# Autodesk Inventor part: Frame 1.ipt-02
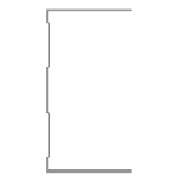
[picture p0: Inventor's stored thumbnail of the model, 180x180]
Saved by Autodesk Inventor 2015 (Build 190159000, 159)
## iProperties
Created: 2015-04
Part Number: Frame 1.ipt-02
Material: Aluminum 6061
Description: Kévin Novo
Document SubType Name: Modeling
Standard: Kevin
Designer: suporte
Standards Organization: Kevin
Language: en-US
Size Designation: (Unnamed 2)
Categories: <MemberInstance><Categories><Category DisplayName="Structural Shapes" InternalName="089c4875-fa83-4c05-b084-43b9cc11f5ed" Mnemonic="GRDR"><CategoryParameter Dis
Density: 2.7 g/cm^3
Appearance: Aluminum - Flat
IsCustomPart: 1
G_W: 50,000 mm
G_H: 75,000 mm
G_L: 518,599 mm
_CCFamilyMember: 2
_CCFamilyDisplayName: Kévin - Kévin Novo
_FrameMemberDoc: Frame Member File
_Version: 15.0.0
_GetPNFromCC: 1
Author: suporte
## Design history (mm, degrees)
node "Start Plane"
node "End Plane"
sketch "Sketch"
  geometry: L1 (24.7, 37.5)-(24.7, 36.9); L2 (24.7, 36.9)-(-24.7, 36.9); L3 (-24.7, -36.9)-(24.7, -36.9); L4 (24.7, -36.9)-(24.7, -37.5); L5 (24.7, -37.5)-(-25.3, -37.5); L6 (-25.3, 37.5)-(24.7, 37.5); L7 (-24.7, 36.9)-(-24.7, 31.9); L8 (-24.7, 31.9)-(-23.3, 30.5); L9 (-23.3, 30.5)-(-23.3, 10.934); L10 (-23.3, 10.934)-(-24.7, 9.534); L11 (-24.7, 9.534)-(-24.7, -9.534); L12 (-24.7, -9.534)-(-23.3, -10.934); L13 (-23.3, -10.934)-(-23.3, -30.5); L14 (-23.3, -30.5)-(-24.7, -31.9); L15 (-24.7, -31.9)-(-24.7, -36.9); L16 (-25.3, -37.5)-(-25.3, -31.651); L17 (-25.3, -31.651)-(-23.9, -30.251); L18 (-23.9, -30.251)-(-23.9, -11.183); L19 (-23.9, -11.183)-(-25.3, -9.783); L20 (-25.3, -9.783)-(-25.3, 9.783); L21 (-25.3, 9.783)-(-23.9, 11.183); L22 (-23.9, 11.183)-(-23.9, 30.251); L23 (-23.9, 30.251)-(-25.3, 31.651); L24 (-25.3, 31.651)-(-25.3, 37.5); L25 (-25.3, 0)-(30.37, 0); 3 further points
  constraints: 50 end point, 10 point on line, 9 parallel, 5 perpendicular, 4 equal length, 3 midpoint, 3 vertical, 2 vertical alignment, 1 collinear, 1 horizontal, 1 horizontal alignment
  dimensions: "d3" = 0.6 distance of L1.start L1.end (= d6); "d5" = 75 distance between parallel lines of L5 L6; "d6" = 0.6 distance between parallel lines of L24 L7 (= d8); "d7" = 0.6 distance between parallel lines of L8 L23 (= d8); "d8" = 0.6 distance between parallel lines of L22 L9 (= d12); "Espessura" = 0.6 distance between parallel lines of L17 L14; "d10" = 0.6 distance between parallel lines of L13 L18 (= Espessura); "d11" = 0.6 distance between parallel lines of L12 L19 (= Espessura); "d12" = 0.6 distance between parallel lines of L21 L10 (= d11); "d13" = 5 distance of L2.end L7.end; "d15" = 135 deg angle of L9 L8; "d16" = 2 distance between parallel lines of L24 L9; "d17" = 50 distance of L6.start L1.start
extrude "Body" join sketch "Sketch" stored distance "d24" = 0.13; taper "d25" = 0 deg
node "Driven Length"
  sketch "Sketch10"
    geometry: L1 (0, 0)-(10, 0) reference
    constraints: 2 end point, 1 horizontal
  workplane "Work Plane7"
  sketch "Sketch11"
    geometry: L1 (-2, 0)-(12, 0) reference; L2 (-2, 518.599)-(12, 518.599) reference
    dimensions: "d27" = 518.59902 distance between parallel lines of L1 L2 (derived)
body "Solid1"
other parameters: "tamanho" = 518.59902, "G_OFFSET_START" = 0 [user parameter; used in 1 equation term], "G_OFFSET_END" = 0 [user parameter; used in 1 equation term], "d22" = 0 (computed from G_OFFSET_START), "d23" = 518.59902 (= tamanho + G_OFFSET_END), "G_L" = 518.59902 (= d27) [user parameter], "d34" = 90 deg
